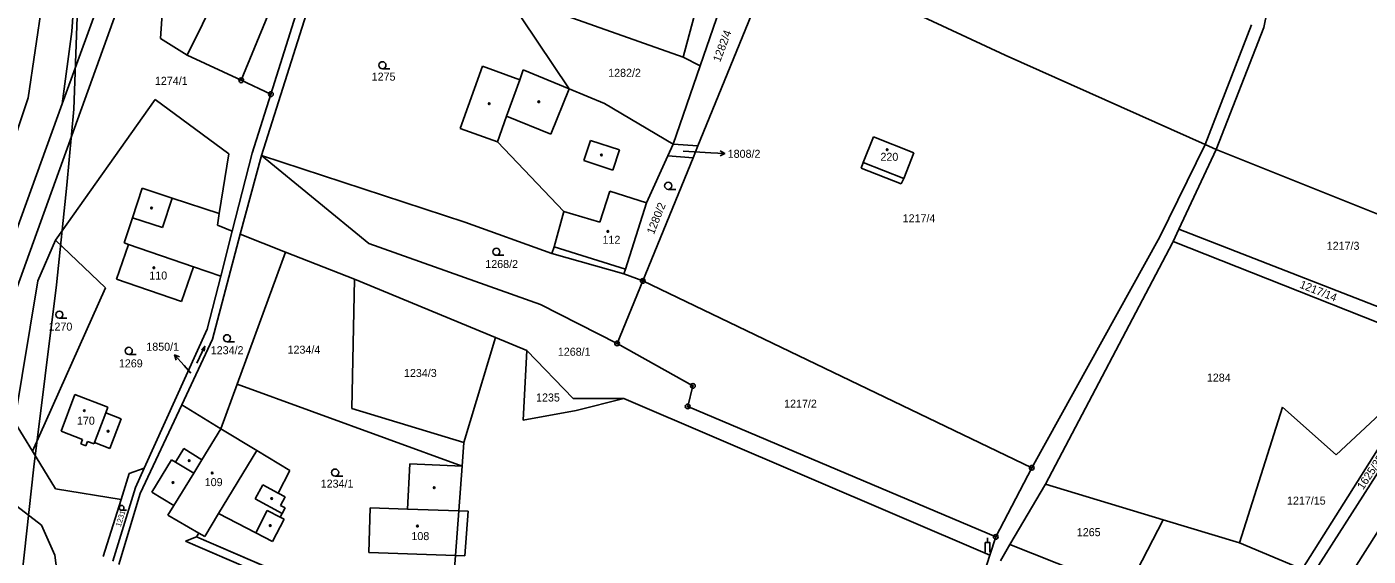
# Model space of a CAD drawing. Extents: x -546762 to -540209, y -1046851 to -1035694.
# Drawn here: x -543591.5 to -543306.6, y -1041408.5 to -1041296.2 of the extents above; entities that cross this region are included whole.
import ezdxf

# ---------------------------------------------------------------- set-up
doc = ezdxf.new("R2010")
doc.units = 0
for name, color, linetype in [('Vrstva 1', 7, 'Continuous'), ('Vrstva 16', 7, 'Continuous'), ('Vrstva 18', 7, 'Continuous'), ('Vrstva 19', 7, 'Continuous'), ('Vrstva 24', 7, 'Continuous'), ('Vrstva 25', 7, 'Continuous'), ('Vrstva 3', 7, 'Continuous'), ('Vrstva 30', 7, 'Continuous'), ('Vrstva 37', 7, 'Continuous'), ('Vrstva 4', 7, 'Continuous'), ('Vrstva 52', 7, 'Continuous'), ('Vrstva 6', 7, 'Continuous')]:
    doc.layers.add(name, color=color, linetype=linetype)

msp = doc.modelspace()

# ---------------------------------------------------------------- linework, layer by layer
at = {"layer": 'Vrstva 1'}
for p, q in [((-543539.71, -1041310.48), (-543531.11, -1041283.23)), ((-543546.02, -1041307.54), (-543539.71, -1041310.48)), ((-543539.71, -1041310.48), (-543543.67, -1041323.02)), ((-543413.88, -1041324.95), (-543411.69, -1041319.5)), ((-543411.69, -1041319.5), (-543403.11, -1041322.91)), ((-543414.31, -1041326.17), (-543413.88, -1041324.95)), ((-543403.11, -1041322.91), (-543405.28, -1041328.36)), ((-543405.85, -1041329.52), (-543414.31, -1041326.17)), ((-543405.28, -1041328.36), (-543405.85, -1041329.52))]:
    msp.add_line(p, q, dxfattribs=at)
for points in [[(-543452.15, -1041302.66), (-543444.45, -1041273.91)], [(-543566.1, -1041275.25), (-543600.22, -1041369.48)], [(-543448.53, -1041304.5), (-543438.87, -1041276.51)], [(-543571.29, -1041277.52), (-543584.03, -1041312.53)], [(-543561.73, -1041277.74), (-543563.17, -1041298.67)], [(-543431.95, -1041279.74), (-543449.02, -1041321.44)], [(-543431.95, -1041279.74), (-543383.75, -1041302.19)], [(-543580.87, -1041280.64), (-543582.02, -1041297.21)], [(-543547.78, -1041282.55), (-543557.52, -1041302.19)], [(-543546.02, -1041307.54), (-543535.21, -1041281.23)], [(-543541.72, -1041323.49), (-543529.03, -1041283.48)], [(-543588.3, -1041291.14), (-543591.25, -1041311.27)], [(-543489.83, -1041289.26), (-543452.15, -1041302.66)], [(-543489.83, -1041289.26), (-543476.35, -1041309.35)], [(-543582.02, -1041297.21), (-543584.03, -1041312.53)], [(-543557.52, -1041302.19), (-543563.17, -1041298.67)], [(-543546.02, -1041307.54), (-543557.52, -1041302.19)], [(-543452.15, -1041302.66), (-543448.53, -1041304.5)], [(-543383.75, -1041302.19), (-543341.28, -1041321.16)], [(-543494.75, -1041304.56), (-543499.5, -1041317.73)], [(-543486.85, -1041307.41), (-543494.75, -1041304.56)], [(-543486.1, -1041305.33), (-543486.85, -1041307.41)], [(-543476.35, -1041309.35), (-543486.1, -1041305.33)], [(-543454.25, -1041321.08), (-543448.53, -1041304.5)], [(-543591.25, -1041311.27), (-543595.64, -1041324.5)], [(-543476.35, -1041309.35), (-543468.83, -1041312.45)], [(-543584.03, -1041312.53), (-543604.75, -1041369.47)], [(-543585.43, -1041341.44), (-543564.26, -1041311.61)], [(-543548.62, -1041323.15), (-543564.26, -1041311.61)], [(-543454.25, -1041321.08), (-543468.83, -1041312.45)], [(-543499.5, -1041317.73), (-543491.6, -1041320.58)], [(-543491.6, -1041320.58), (-543477.5, -1041335.34)], [(-543454.25, -1041321.08), (-543455.39, -1041323.59)], [(-543454.25, -1041321.08), (-543449.02, -1041321.44)], [(-543449.02, -1041321.44), (-543450.05, -1041323.96)], [(-543350.91, -1041340.76), (-543341.28, -1041321.16)], [(-543346.86, -1041339.11), (-543338.94, -1041322.23)], [(-543341.28, -1041321.16), (-543338.94, -1041322.23)], [(-543338.94, -1041322.23), (-543279.44, -1041346)], [(-543550.66, -1041335.82), (-543548.62, -1041323.15)], [(-543543.67, -1041323.02), (-543547.9, -1041339.51)], [(-543546.24, -1041340.17), (-543541.72, -1041323.49)], [(-543541.72, -1041323.49), (-543518.94, -1041342.13)], [(-543498.48, -1041337.6), (-543541.72, -1041323.49)], [(-543450.05, -1041323.96), (-543460.73, -1041350.09)], [(-543455.39, -1041323.59), (-543459.93, -1041333.56)], [(-543450.05, -1041323.96), (-543455.39, -1041323.59)], [(-543567.07, -1041330.43), (-543569.13, -1041336.7)], [(-543560.7, -1041332.52), (-543567.07, -1041330.43)], [(-543550.66, -1041335.82), (-543560.7, -1041332.52)], [(-543459.93, -1041333.56), (-543464.41, -1041347.63)], [(-543569.13, -1041336.7), (-543570.88, -1041342.04)], [(-543551.05, -1041338.27), (-543550.66, -1041335.82)], [(-543477.5, -1041335.34), (-543479.57, -1041342.86)], [(-543547.9, -1041339.51), (-543551.05, -1041338.27)], [(-543547.9, -1041339.51), (-543550.36, -1041349.08)], [(-543480.06, -1041344.28), (-543498.48, -1041337.6)], [(-543348.09, -1041341.74), (-543346.86, -1041339.11)], [(-543589.21, -1041350.11), (-543585.43, -1041341.44)], [(-543574.84, -1041351.56), (-543585.43, -1041341.44)], [(-543569.96, -1041342.36), (-543572.49, -1041349.73)], [(-543570.88, -1041342.04), (-543569.96, -1041342.36)], [(-543552.12, -1041362.48), (-543546.24, -1041340.17)], [(-543536.59, -1041343.97), (-543546.24, -1041340.17)], [(-543518.94, -1041342.13), (-543482.41, -1041355.1)], [(-543378.09, -1041389.73), (-543350.91, -1041340.76)], [(-543375.19, -1041393.23), (-543348.21, -1041341.99)], [(-543348.21, -1041341.99), (-543348.09, -1041341.74)], [(-543536.59, -1041343.97), (-543546.88, -1041372.01)], [(-543521.93, -1041349.74), (-543536.59, -1041343.97)], [(-543480.06, -1041344.28), (-543479.57, -1041342.86)], [(-543464.77, -1041348.56), (-543480.06, -1041344.28)], [(-543556.15, -1041347.09), (-543558.68, -1041354.47)], [(-543550.36, -1041349.08), (-543556.15, -1041347.09)], [(-543464.77, -1041348.56), (-543464.41, -1041347.63)], [(-543594.14, -1041379.99), (-543589.21, -1041350.11)], [(-543558.68, -1041354.47), (-543572.49, -1041349.73)], [(-543550.36, -1041349.08), (-543553.25, -1041360.36)], [(-543492.02, -1041362.08), (-543521.93, -1041349.74)], [(-543466.16, -1041363.35), (-543460.73, -1041350.09)], [(-543464.77, -1041348.56), (-543460.73, -1041350.09)], [(-543460.73, -1041350.09), (-543378.09, -1041389.73)], [(-543590.34, -1041386.19), (-543574.84, -1041351.56)], [(-543482.41, -1041355.1), (-543466.16, -1041363.35)], [(-543566.62, -1041389.79), (-543553.25, -1041360.36)], [(-543558.64, -1041376.41), (-543552.12, -1041362.48)], [(-543492.02, -1041362.08), (-543498.7, -1041384.38)], [(-543485.34, -1041364.83), (-543492.02, -1041362.08)], [(-543475.49, -1041375.02), (-543485.34, -1041364.83)], [(-543450.07, -1041372.36), (-543466.16, -1041363.35)], [(-543288.43, -1041365.54), (-543318.34, -1041412.21)], [(-543293.78, -1041368.69), (-543320.67, -1041411.23)], [(-543311.97, -1041414.88), (-543282.4, -1041368.38)], [(-543546.88, -1041372.01), (-543550.34, -1041381.45)], [(-543499.08, -1041389.42), (-543546.88, -1041372.01)], [(-543451.18, -1041376.73), (-543450.07, -1041372.36)], [(-543581.32, -1041374.22), (-543584.27, -1041381.98)], [(-543581.32, -1041374.22), (-543574.31, -1041376.88)], [(-543574.31, -1041376.88), (-543574.77, -1041378.09)], [(-543567.44, -1041395.21), (-543558.64, -1041376.41)], [(-543550.34, -1041381.45), (-543558.64, -1041376.41)], [(-543475.49, -1041375.02), (-543464.74, -1041375.01)], [(-543386.99, -1041408.3), (-543464.74, -1041375.01)], [(-543385.74, -1041404.41), (-543451.18, -1041376.73)], [(-543574.77, -1041378.09), (-543571.5, -1041379.34)], [(-543571.5, -1041379.34), (-543573.89, -1041385.65)], [(-543590.34, -1041386.19), (-543594.14, -1041379.99)], [(-543579.7, -1041383.75), (-543584.27, -1041381.98)], [(-543550.34, -1041381.45), (-543554.37, -1041388.03)], [(-543550.34, -1041381.45), (-543542.7, -1041386.09)], [(-543579.7, -1041383.75), (-543580.06, -1041384.68)], [(-543579.03, -1041385.08), (-543580.06, -1041384.68)], [(-543578.67, -1041384.14), (-543579.03, -1041385.08)], [(-543578.67, -1041384.14), (-543577.27, -1041384.69)], [(-543577.17, -1041384.41), (-543577.27, -1041384.69)], [(-543573.89, -1041385.65), (-543577.17, -1041384.41)], [(-543498.7, -1041384.38), (-543499.08, -1041389.42)], [(-543585.45, -1041394.18), (-543590.34, -1041386.19)], [(-543560.83, -1041388.02), (-543564.97, -1041394.9)], [(-543559.97, -1041388.54), (-543560.83, -1041388.02)], [(-543559.97, -1041388.54), (-543558.17, -1041385.65)], [(-543558.17, -1041385.65), (-543554.37, -1041388.03)], [(-543542.7, -1041386.09), (-543535.69, -1041390.35)], [(-543603.86, -1041390.13), (-543588.44, -1041401.93)], [(-543569.78, -1041390.95), (-543571.52, -1041396.44)], [(-543566.62, -1041389.79), (-543569.78, -1041390.95)], [(-543568.5, -1041393.94), (-543566.62, -1041389.79)], [(-543535.69, -1041390.35), (-543538.16, -1041395.12)], [(-543510.17, -1041388.93), (-543510.7, -1041398.52)], [(-543499.08, -1041389.42), (-543510.17, -1041388.93)], [(-543499.08, -1041389.42), (-543499.81, -1041398.89)], [(-543378.09, -1041389.73), (-543385.74, -1041404.41)], [(-543568.5, -1041393.94), (-543573.29, -1041409.58)], [(-543382.73, -1041406.01), (-543375.19, -1041393.23)], [(-543585.45, -1041394.18), (-543571.52, -1041396.44)], [(-543571.52, -1041396.44), (-543575.35, -1041408.53)], [(-543567.44, -1041395.21), (-543572.02, -1041410.25)], [(-543564.97, -1041394.9), (-543560.32, -1041397.74)], [(-543538.16, -1041395.12), (-543536.71, -1041395.91)], [(-543536.71, -1041395.91), (-543537.64, -1041397.71)], [(-543560.32, -1041397.74), (-543561.57, -1041399.79)], [(-543550.81, -1041399.45), (-543553.77, -1041404.32)], [(-543542.91, -1041403.54), (-543550.81, -1041399.45)], [(-543537.3, -1041399.46), (-543537.72, -1041400.25)], [(-543537.64, -1041397.71), (-543536.66, -1041398.21)], [(-543536.66, -1041398.21), (-543537.3, -1041399.46)], [(-543518.59, -1041398.25), (-543518.92, -1041407.74)], [(-543510.7, -1041398.52), (-543518.59, -1041398.25)], [(-543499.81, -1041398.89), (-543497.81, -1041398.96)], [(-543497.81, -1041398.96), (-543498.53, -1041408.44)], [(-543588.44, -1041401.93), (-543585.6, -1041408.27)], [(-543561.57, -1041399.79), (-543555.02, -1041403.59)], [(-543536.92, -1041400.67), (-543539.35, -1041405.38)], [(-543537.72, -1041400.25), (-543536.92, -1041400.67)], [(-543555.52, -1041404.4), (-543557.85, -1041405.3)], [(-543513.78, -1041424.24), (-543557.85, -1041405.3)], [(-543555.02, -1041403.59), (-543555.52, -1041404.4)], [(-543513.46, -1041422.47), (-543555.52, -1041404.4)], [(-543555.02, -1041403.59), (-543553.77, -1041404.32)], [(-543539.35, -1041405.38), (-543542.91, -1041403.54)], [(-543385.74, -1041404.41), (-543386.99, -1041408.3)], [(-543518.92, -1041407.74), (-543500.53, -1041408.37)], [(-543384.76, -1041409.46), (-543382.73, -1041406.01)], [(-543585.6, -1041408.27), (-543584.7, -1041415.35)], [(-543500.53, -1041408.37), (-543501.98, -1041427.41)], [(-543500.53, -1041408.37), (-543498.53, -1041408.44)], [(-543386.99, -1041408.3), (-543397.58, -1041441.33)]]:
    msp.add_lwpolyline(points, dxfattribs=at)
at = {"layer": 'Vrstva 16'}
for p, q in [((-543446.28, -1041322.91), (-543443.29, -1041323.09)), ((-543558.15, -1041368.03), (-543560.16, -1041365.81))]:
    msp.add_line(p, q, dxfattribs=at)
for points in [[(-543452.15, -1041322.56), (-543446.28, -1041322.91)], [(-543444.25, -1041322.53), (-543443.29, -1041323.09), (-543444.31, -1041323.53)], [(-543559.86, -1041366.88), (-543560.16, -1041365.81), (-543559.12, -1041366.21)], [(-543556.68, -1041369.65), (-543558.15, -1041368.03)]]:
    msp.add_lwpolyline(points, dxfattribs=at)
at = {"layer": 'Vrstva 24'}
for centre, radius in [((-543546.02, -1041307.54), 0.5), ((-543546.02, -1041307.54), 0.1), ((-543539.71, -1041310.48), 0.5), ((-543539.71, -1041310.48), 0.1), ((-543460.73, -1041350.09), 0.5), ((-543460.73, -1041350.09), 0.1), ((-543466.16, -1041363.35), 0.5), ((-543466.16, -1041363.35), 0.1), ((-543450.07, -1041372.36), 0.5), ((-543450.07, -1041372.36), 0.1), ((-543451.18, -1041376.73), 0.5), ((-543451.18, -1041376.73), 0.1), ((-543378.09, -1041389.73), 0.5), ((-543378.09, -1041389.73), 0.1), ((-543385.74, -1041404.41), 0.5), ((-543385.74, -1041404.41), 0.1)]:
    msp.add_circle(centre, radius, dxfattribs=at)
at = {"layer": 'Vrstva 25'}
for p, q in [((-543516.01, -1041305.09), (-543514.41, -1041305.09)), ((-543455.32, -1041330.67), (-543453.72, -1041330.67)), ((-543491.81, -1041344.66), (-543490.21, -1041344.66)), ((-543584.64, -1041358), (-543583.04, -1041358)), ((-543549.02, -1041363.01), (-543547.42, -1041363.01)), ((-543569.89, -1041365.68), (-543568.29, -1041365.68)), ((-543526.06, -1041391.5), (-543524.46, -1041391.5)), ((-543571.42, -1041398.74), (-543570.35, -1041398.74))]:
    msp.add_line(p, q, dxfattribs=at)
for points in [[(-543555.47, -1041367.58), (-543553.75, -1041363.96), (-543554.48, -1041364.72)], [(-543553.75, -1041363.96), (-543553.88, -1041365.01)], [(-543387.49, -1041405.61), (-543387.49, -1041404.61)], [(-543387.99, -1041407.61), (-543387.99, -1041405.61), (-543386.99, -1041405.61), (-543386.99, -1041407.61)]]:
    msp.add_lwpolyline(points, dxfattribs=at)
for centre, radius in [((-543516.01, -1041304.34), 0.75), ((-543493.33, -1041312.5), 0.175), ((-543482.8, -1041312.1), 0.175), ((-543408.81, -1041322.26), 0.175), ((-543469.49, -1041323.39), 0.175), ((-543455.32, -1041329.92), 0.75), ((-543565.05, -1041334.63), 0.175), ((-543468.14, -1041339.61), 0.175), ((-543491.81, -1041343.91), 0.75), ((-543564.57, -1041347.31), 0.175), ((-543584.64, -1041357.25), 0.75), ((-543549.02, -1041362.26), 0.75), ((-543569.89, -1041364.93), 0.75), ((-543579.35, -1041377.63), 0.175), ((-543574.28, -1041381.98), 0.175), ((-543557.06, -1041388.23), 0.175), ((-543552.17, -1041390.83), 0.175), ((-543526.06, -1041390.75), 0.75), ((-543560.5, -1041392.88), 0.175), ((-543505.02, -1041393.97), 0.175), ((-543539.55, -1041396.26), 0.175), ((-543571.42, -1041398.24), 0.503), ((-543539.86, -1041402), 0.175), ((-543508.58, -1041402.12), 0.175)]:
    msp.add_circle(centre, radius, dxfattribs=at)
at = {"layer": 'Vrstva 3'}
for points in [[(-543413.88, -1041324.95), (-543411.69, -1041319.5)], [(-543411.69, -1041319.5), (-543403.11, -1041322.91)], [(-543413.88, -1041324.95), (-543405.28, -1041328.36)], [(-543403.11, -1041322.91), (-543405.28, -1041328.36)], [(-543467.74, -1041331.07), (-543469.84, -1041337.65)], [(-543459.93, -1041333.56), (-543467.74, -1041331.07)], [(-543459.93, -1041333.56), (-543464.41, -1041347.63)], [(-543477.5, -1041335.34), (-543479.57, -1041342.86)], [(-543477.5, -1041335.34), (-543469.84, -1041337.65)], [(-543569.96, -1041342.36), (-543572.49, -1041349.73)], [(-543556.15, -1041347.09), (-543569.96, -1041342.36)], [(-543464.41, -1041347.63), (-543479.57, -1041342.86)], [(-543556.15, -1041347.09), (-543558.68, -1041354.47)], [(-543558.68, -1041354.47), (-543572.49, -1041349.73)], [(-543581.32, -1041374.22), (-543584.27, -1041381.98)], [(-543581.32, -1041374.22), (-543574.31, -1041376.88)], [(-543574.31, -1041376.88), (-543574.77, -1041378.09)], [(-543574.77, -1041378.09), (-543577.17, -1041384.41)], [(-543579.7, -1041383.75), (-543584.27, -1041381.98)], [(-543550.34, -1041381.45), (-543554.37, -1041388.03)], [(-543550.34, -1041381.45), (-543542.7, -1041386.09)], [(-543579.7, -1041383.75), (-543580.06, -1041384.68)], [(-543579.03, -1041385.08), (-543580.06, -1041384.68)], [(-543578.67, -1041384.14), (-543579.03, -1041385.08)], [(-543578.67, -1041384.14), (-543577.27, -1041384.69)], [(-543577.17, -1041384.41), (-543577.27, -1041384.69)], [(-543554.37, -1041388.03), (-543556.11, -1041390.86)], [(-543542.7, -1041386.09), (-543550.81, -1041399.45)], [(-543556.11, -1041390.86), (-543560.32, -1041397.74)], [(-543560.32, -1041397.74), (-543561.57, -1041399.79)], [(-543550.81, -1041399.45), (-543553.77, -1041404.32)], [(-543518.59, -1041398.25), (-543518.92, -1041407.74)], [(-543510.7, -1041398.52), (-543518.59, -1041398.25)], [(-543499.81, -1041398.89), (-543510.7, -1041398.52)], [(-543499.81, -1041398.89), (-543500.53, -1041408.37)], [(-543561.57, -1041399.79), (-543555.02, -1041403.59)], [(-543555.02, -1041403.59), (-543553.77, -1041404.32)], [(-543518.92, -1041407.74), (-543500.53, -1041408.37)]]:
    msp.add_lwpolyline(points, dxfattribs=at)
at = {"layer": 'Vrstva 30'}
for p, q in [((-543557.85, -1041405.3), (-543555.52, -1041404.4)), ((-543515.08, -1041423.68), (-543557.85, -1041405.3)), ((-543555.52, -1041404.4), (-543538.77, -1041411.6))]:
    msp.add_line(p, q, dxfattribs=at)
at = {"layer": 'Vrstva 37'}
for centre in [(-543408.81, -1041322.26), (-543468.14, -1041339.61), (-543564.57, -1041347.31), (-543579.35, -1041377.63), (-543552.17, -1041390.83), (-543508.58, -1041402.12)]:
    msp.add_circle(centre, 0.175, dxfattribs=at)
at = {"layer": 'Vrstva 4'}
msp.add_line((-543413.88, -1041324.95), (-543405.28, -1041328.36), dxfattribs=at)
for points in [[(-543486.85, -1041307.41), (-543489.64, -1041315.14)], [(-543480.28, -1041319), (-543476.35, -1041309.35)], [(-543489.64, -1041315.14), (-543491.6, -1041320.58)], [(-543489.64, -1041315.14), (-543480.28, -1041319)], [(-543471.81, -1041320.31), (-543473.21, -1041324.58)], [(-543471.81, -1041320.31), (-543465.68, -1041322.31)], [(-543465.68, -1041322.31), (-543467.08, -1041326.59)], [(-543473.21, -1041324.58), (-543467.08, -1041326.59)], [(-543467.74, -1041331.07), (-543469.84, -1041337.65)], [(-543459.93, -1041333.56), (-543467.74, -1041331.07)], [(-543560.7, -1041332.52), (-543562.76, -1041338.79)], [(-543569.13, -1041336.7), (-543562.76, -1041338.79)], [(-543477.5, -1041335.34), (-543469.84, -1041337.65)], [(-543556.15, -1041347.09), (-543569.96, -1041342.36)], [(-543464.41, -1041347.63), (-543479.57, -1041342.86)], [(-543574.77, -1041378.09), (-543577.17, -1041384.41)], [(-543554.37, -1041388.03), (-543556.11, -1041390.86)], [(-543542.7, -1041386.09), (-543550.81, -1041399.45)], [(-543556.11, -1041390.86), (-543560.32, -1041397.74)], [(-543559.97, -1041388.54), (-543556.11, -1041390.86)], [(-543541.41, -1041393.36), (-543543.03, -1041396.35)], [(-543538.16, -1041395.12), (-543541.41, -1041393.36)], [(-543543.03, -1041396.35), (-543537.3, -1041399.46)], [(-543540.47, -1041398.83), (-543542.91, -1041403.54)], [(-543540.47, -1041398.83), (-543537.72, -1041400.25)], [(-543499.81, -1041398.89), (-543510.7, -1041398.52)], [(-543499.81, -1041398.89), (-543500.53, -1041408.37)]]:
    msp.add_lwpolyline(points, dxfattribs=at)
at = {"layer": 'Vrstva 52'}
msp.add_lwpolyline([(-543580.05, -1041272.47), (-543581.53, -1041313.66), (-543583.02, -1041329.8), (-543585.24, -1041350.95), (-543590.06, -1041389.55), (-543594.14, -1041427.03), (-543597.48, -1041468.96), (-543599.71, -1041509.04), (-543600.5, -1041537.54), (-543600.29, -1041558.96), (-543600.71, -1041581.44), (-543602.41, -1041608.37), (-543604.74, -1041627.67)], dxfattribs=at)
at = {"layer": 'Vrstva 6'}
for points in [[(-543328.81, -1041296.37), (-543325.21, -1041278.57)], [(-543341.28, -1041321.16), (-543331.43, -1041295.8)], [(-543338.94, -1041322.23), (-543328.81, -1041296.37)], [(-543346.86, -1041339.11), (-543289.25, -1041361.51)], [(-543348.09, -1041341.74), (-543291.02, -1041364.32)], [(-543522.5, -1041377.15), (-543521.93, -1041349.74)], [(-543485.34, -1041364.83), (-543486.15, -1041379.62)], [(-543313.47, -1041386.97), (-543293.78, -1041368.69)], [(-543474.87, -1041377.59), (-543464.74, -1041375.01)], [(-543324.85, -1041376.88), (-543333.94, -1041405.67)], [(-543313.47, -1041386.97), (-543324.85, -1041376.88)], [(-543498.7, -1041384.38), (-543522.5, -1041377.15)], [(-543486.15, -1041379.62), (-543474.87, -1041377.59)], [(-543350.19, -1041400.77), (-543375.19, -1041393.23)], [(-543357.98, -1041415.87), (-543350.19, -1041400.77)], [(-543333.94, -1041405.67), (-543350.19, -1041400.77)], [(-543382.73, -1041406.01), (-543357.98, -1041415.87)], [(-543333.94, -1041405.67), (-543320.67, -1041411.23)]]:
    msp.add_lwpolyline(points, dxfattribs=at)

# ---------------------------------------------------------------- texts
at = {"layer": 'Vrstva 16'}
for s, p in [('1808/2', (-543442.68, -1041323.98)), ('1850/1', (-543566.17, -1041364.91))]:
    msp.add_text(s, height=1.7, dxfattribs=at).set_placement(p)
at = {"layer": 'Vrstva 18'}
for s, height, rotation, p in [('1282/4', 1.7, 69.3263, (-543444.29, -1041303.8)), ('1280/2', 1.7, 68.2307, (-543458.37, -1041340.36)), ('1217/14', 1.7, 338.4301, (-543321.34, -1041351.5)), ('1625/35', 1.7, 56.3099, (-543307.71, -1041394.53)), ('1231', 1.14, 73.3264, (-543571.6, -1041402.35))]:
    msp.add_text(s, height=height, rotation=rotation, dxfattribs=at).set_placement(p)
for s, height, p in [('1282/2', 1.7, (-543468.07, -1041306.8)), ('1274/1', 1.7, (-543564.34, -1041308.5)), ('1275', 1.7, (-543518.3, -1041307.61)), ('1808/2', 0.1, (-543452.36, -1041322.56)), ('1217/4', 1.7, (-543405.52, -1041337.66)), ('1217/3', 1.7, (-543315.45, -1041343.5)), ('1268/2', 1.7, (-543494.17, -1041347.36)), ('1270', 1.7, (-543586.94, -1041360.64)), ('1234/2', 1.7, (-543552.48, -1041365.65)), ('1234/4', 1.7, (-543536.17, -1041365.53)), ('1268/1', 1.7, (-543478.76, -1041365.97)), ('1269', 1.7, (-543571.99, -1041368.44)), ('1850/1', 0.1, (-543556.88, -1041369.65)), ('1234/3', 1.7, (-543511.44, -1041370.48)), ('1284', 1.7, (-543340.9, -1041371.46)), ('1235', 1.7, (-543483.39, -1041375.68)), ('1217/2', 1.7, (-543430.7, -1041376.99)), ('1234/1', 1.7, (-543529.13, -1041393.96)), ('1217/15', 1.7, (-543323.89, -1041397.56)), ('1265', 1.7, (-543368.53, -1041404.25))]:
    msp.add_text(s, height=height, dxfattribs=at).set_placement(p)
at = {"layer": 'Vrstva 19'}
for s, p in [('220', (-543410.24, -1041324.62)), ('112', (-543469.27, -1041342.22)), ('110', (-543565.53, -1041349.8)), ('170', (-543580.9, -1041380.6)), ('109', (-543553.76, -1041393.63)), ('108', (-543509.86, -1041405.08))]:
    msp.add_text(s, height=1.7, dxfattribs=at).set_placement(p)

doc.saveas('drawing.dxf')
